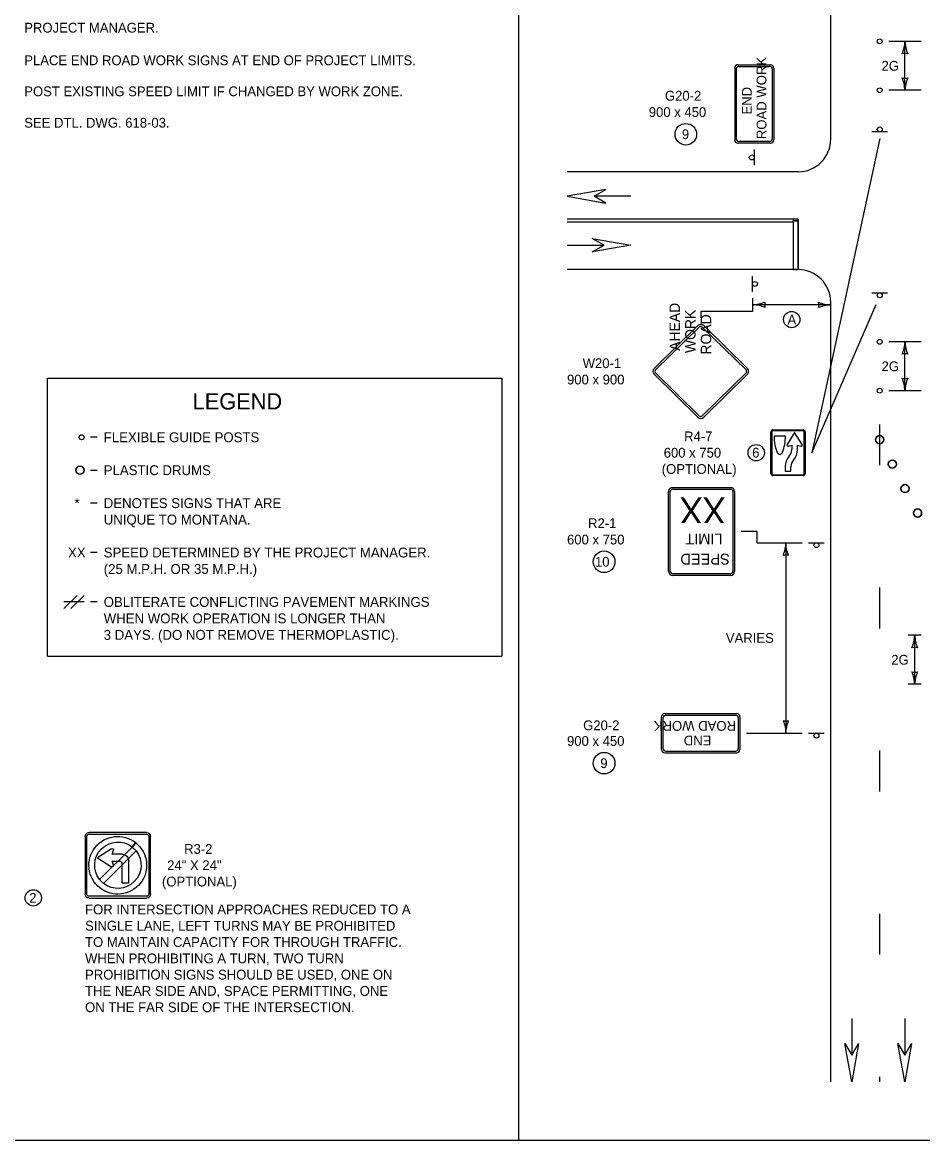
# Model space of a CAD drawing. Extents: x 49991.4 to 50021, y 49987.6 to 50011.4.
# Drawn here: x 50005.02 to 50010.55, y 49987.8 to 49994.66 of the extents above; entities that cross this region are included whole.
import ezdxf

# ---------------------------------------------------------------- set-up
doc = ezdxf.new("R2010")
doc.units = 0
for name, color, linetype in [('Level 1', 7, 'Continuous'), ('Level 2', 7, 'Continuous'), ('Level 25', 7, 'Continuous'), ('Level 3', 7, 'Continuous')]:
    doc.layers.add(name, color=color, linetype=linetype)

# ---------------------------------------------------------------- blocks, each defined once
blk = doc.blocks.new('R3.1')
at = {"layer": 'Level 25'}
for p, q in [((-41.1, 34.2), (-38.9, 34.2)), ((-38.9, 34.2), (-41.1, 34.2)), ((-41.1, -39.9), (-41.1, 34.2)), ((-41.1, 34.2), (-38.9, 34.2)), ((-38.9, 34.2), (-38.9, -39.9)), ((-35.8, 39.5), (38.3, 39.5)), ((38.3, 37.3), (-35.8, 37.3)), ((41.4, -39.9), (41.4, 34.2)), ((43.6, 34.2), (43.6, -39.9)), ((-17.3, 20.7), (-22.3, 15.7)), ((-17.3, 20.7), (-22.3, 15.7)), ((-22.3, 15.7), (19.8, -26.4)), ((-21.9, 26.2), (-17.3, 20.7)), ((-17.2, 20.8), (-21.8, 26.3)), ((24.8, -21.4), (-17.3, 20.7)), ((8.4, 11.3), (6.7, 16.5)), ((9.3, 18.5), (27.7, 6.9)), ((9.3, 18.5), (9.3, 18.5)), ((-12.9, -25.7), (-12.9, 3.3)), ((-4.9, 11.3), (8.4, 11.3)), ((8.4, 2.5), (-1.1, 2.5)), ((6.7, -2.7), (8.4, 2.5)), ((27.7, 6.9), (9.3, -4.7)), ((-4.1, -0.5), (-4.1, -25.7)), ((-4.1, -25.7), (-12.9, -25.7)), ((19.8, -26.4), (24.8, -21.4)), ((19.8, -26.4), (24.8, -21.4)), ((-35.8, -42.9), (38.3, -42.9)), ((38.3, -45.2), (-35.8, -45.2))]:
    blk.add_line(p, q, dxfattribs=at)
for centre, radius, start, end in [((-35.8, 34.2), 5.29, 90, 180), ((-35.8, 34.2), 3.09, 90, 180), ((1.3, -2.9), 37.3, 128.573, 128.3407), ((38.3, 34.2), 5.29, 0, 90), ((38.3, 34.2), 3.09, 0, 90), ((1.2, -2.8), 30, 141.7565, 308.2429), ((1.2, -2.8), 30, 321.7571, 127.9547), ((8.4, 17), 1.75, 57.757, 197.6186), ((1.2, -2.8), 30, 44.2869, 44.4163), ((-4.9, 3.3), 8, 90, 180), ((-1.1, -0.5), 3, 90, 180), ((8.4, -3.2), 1.75, 162.3804, 302.2438), ((1.2, -2.8), 30, 220.8564, 220.8714), ((-35.8, -39.9), 5.29, 180, 270), ((-35.8, -39.9), 3.09, 180, 270), ((38.3, -39.9), 5.29, 270, 0), ((38.3, -39.9), 3.09, 270, 0)]:
    blk.add_arc(centre, radius, start, end, dxfattribs=at)
blk = doc.blocks.new('R4.7')
at = {"layer": 'Level 25'}
for p, q in [((-42.9, -53.4), (-42.9, 48.9)), ((-40.7, 48.9), (-40.7, -53.4)), ((-37.6, 54.2), (36.5, 54.2)), ((36.5, 52), (-37.6, 52)), ((-6.8, 38.4), (-35, 38.4)), ((15.6, 47.6), (-3, 18.2)), ((34.1, 18.2), (15.6, 47.6)), ((39.5, -53.4), (39.5, 48.9)), ((41.7, 48.9), (41.7, -53.4)), ((0.3, 14.1), (8.5, 16.7)), ((8.5, 16.7), (8.5, 5.4)), ((22.6, 5.4), (22.6, 16.7)), ((22.6, 16.7), (30.9, 14.1)), ((-7.6, -36.9), (-7.6, -48.1)), ((-7.6, -48.1), (6.5, -48.1)), ((6.5, -48.1), (6.5, -36.9)), ((-37.6, -56.5), (36.5, -56.5)), ((36.5, -58.7), (-37.6, -58.7))]:
    blk.add_line(p, q, dxfattribs=at)
blk.add_lwpolyline([(15.8, 47.3), (15.5, 47.6)], dxfattribs=at)
for centre, radius, start, end in [((-37.6, 48.9), 5.29, 90, 180), ((-37.6, 48.9), 3.09, 90, 180), ((70.9, 38), 105.8, 179.7952, 201.7879), ((-112.6, 38), 105.8, 338.2124, 0.205), ((36.5, 48.9), 5.29, 0, 90), ((36.5, 48.9), 3.09, 0, 90), ((-0.6, 16.8), 2.79, 147.757, 287.6186), ((-16.2, 5.4), 24.7, 318.1901, 0), ((-16.2, 5.4), 38.8, 318.1901, 0), ((31.8, 16.8), 2.79, 252.3804, 32.2438), ((-20.9, 1.3), 7.06, 201.7877, 338.2132), ((31.2, -36.9), 38.8, 138.1903, 180), ((31.2, -36.9), 24.7, 138.1903, 180), ((-37.6, -53.4), 5.29, 180, 270), ((-37.6, -53.4), 3.09, 180, 270), ((36.5, -53.4), 3.09, 270, 0), ((36.5, -53.4), 5.29, 270, 0)]:
    blk.add_arc(centre, radius, start, end, dxfattribs=at)
blk = doc.blocks.new('ARR')
at = {"layer": 'Level 3'}
for centre, radius, start, end in [((1.5, 37), 37.1, 247.456, 267.6395), ((-21.4, 0), 9.13, 342.1388, 17.8612), ((1.9, -38.8), 38.8, 92.8273, 112.0772)]:
    blk.add_arc(centre, radius, start, end, dxfattribs=at)
blk = doc.blocks.new('G20-2')
at = {"layer": 'Level 1'}
for p, q in [((-0.2403, -0.1004), (-0.2403, 0.0996)), ((-0.2303, -0.0954), (-0.2303, 0.0946)), ((0.2197, 0.1196), (-0.2203, 0.1196)), ((0.2147, 0.1096), (-0.2153, 0.1096)), ((0.2297, 0.0946), (0.2297, -0.0954)), ((0.2397, 0.0996), (0.2397, -0.1004)), ((0.2196, -0.1204), (-0.2204, -0.1204)), ((0.2147, -0.1104), (-0.2153, -0.1104))]:
    blk.add_line(p, q, dxfattribs=at)
for centre, radius, start, end in [((-0.2203, 0.0996), 0.02, 90, 180), ((-0.2153, 0.0946), 0.015, 90, 180), ((0.2147, 0.0946), 0.015, 360, 90), ((0.2197, 0.0996), 0.02, 360, 90), ((-0.2204, -0.1004), 0.02, 180, 270), ((-0.2153, -0.0954), 0.015, 180, 270), ((0.2147, -0.0954), 0.015, 270, 360), ((0.2196, -0.1004), 0.02, 270, 360)]:
    blk.add_arc(centre, radius, start, end, dxfattribs=at)
for s, p in [('END', (-0.0655, 0.015)), ('ROAD WORK', (-0.2162, -0.075))]:
    blk.add_text(s, height=0.06, rotation=360, dxfattribs=at).set_placement(p)

msp = doc.modelspace()

# ---------------------------------------------------------------- linework, layer by layer
at = {"layer": 'Level 1'}
for p, q in [((50008.0668, 49998.9992), (50008.0668, 49987.7988)), ((50009.9832, 49993.9404), (50009.9832, 49998.6295)), ((50010.3314, 49993.9851), (50010.2354, 49993.9851)), ((50009.5136, 49993.8764), (50009.5136, 49993.7804)), ((50009.7832, 49993.7404), (50008.3664, 49993.7404)), ((50008.7565, 49993.5905), (50008.5306, 49993.5905)), ((50008.7565, 49993.5901), (50008.5306, 49993.5901)), ((50009.7832, 49993.4505), (50008.3664, 49993.4505)), ((50009.7532, 49993.4305), (50008.3664, 49993.4305)), ((50009.7532, 49993.4505), (50009.7532, 49993.1404)), ((50009.7532, 49993.4405), (50009.7832, 49993.4405)), ((50009.7832, 49993.4505), (50009.7832, 49993.1404)), ((50008.3664, 49993.2905), (50008.5923, 49993.2905)), ((50008.3664, 49993.2901), (50008.5923, 49993.2901)), ((50009.7832, 49993.1404), (50008.3664, 49993.1404)), ((50009.5032, 49993.0044), (50009.5032, 49993.1004)), ((50010.2353, 49992.9977), (50010.3313, 49992.9977)), ((50009.9832, 49988.1586), (50009.9832, 49992.9404)), ((50008.8993, 49992.5343), (50009.1676, 49992.7971)), ((50008.9079, 49992.5255), (50009.1762, 49992.7883)), ((50009.1949, 49992.7883), (50009.4631, 49992.5255)), ((50009.2035, 49992.7971), (50009.4717, 49992.5343)), ((50009.1676, 49992.2355), (50008.8993, 49992.4983)), ((50009.1762, 49992.2443), (50008.9079, 49992.5071)), ((50009.4631, 49992.5071), (50009.1949, 49992.2443)), ((50009.4717, 49992.4983), (50009.2035, 49992.2355)), ((50010.2833, 49991.9404), (50010.2833, 49992.1904)), ((50010.2583, 49992.0977), (50010.2583, 49992.0977)), ((50010.3358, 49991.9477), (50010.3358, 49991.9477)), ((50008.9879, 49991.2902), (50008.9879, 49991.7797)), ((50008.9984, 49991.2902), (50008.9984, 49991.7797)), ((50009.0132, 49991.805), (50009.3676, 49991.805)), ((50009.0132, 49991.7945), (50009.3676, 49991.7945)), ((50009.3824, 49991.7797), (50009.3824, 49991.2902)), ((50009.393, 49991.7797), (50009.393, 49991.2902)), ((50010.4133, 49991.7977), (50010.4133, 49991.7977)), ((50010.4907, 49991.6477), (50010.4907, 49991.6477)), ((50009.8472, 49991.4657), (50009.9432, 49991.4657)), ((50009.3676, 49991.2755), (50009.0132, 49991.2755)), ((50009.3676, 49991.2649), (50009.0132, 49991.2649)), ((50009.1904, 49991.2649), (50009.1904, 49991.2649)), ((50005.2781, 49991.062), (50005.3589, 49991.1428)), ((50005.321, 49991.062), (50005.4018, 49991.1428)), ((50010.2833, 49990.9404), (50010.2833, 49991.1904)), ((50005.4018, 49991.1024), (50005.2781, 49991.1024)), ((50009.8472, 49990.2977), (50009.9432, 49990.2977)), ((50010.2833, 49989.9404), (50010.2833, 49990.1904)), ((50010.2833, 49988.9404), (50010.2833, 49989.1904)), ((50010.1119, 49988.5487), (50010.1119, 49988.3228)), ((50010.1123, 49988.5487), (50010.1123, 49988.3228)), ((50010.4366, 49988.5487), (50010.4366, 49988.3228)), ((50010.437, 49988.5487), (50010.437, 49988.3228)), ((50010.2833, 49988.1586), (50010.2833, 49988.1904))]:
    msp.add_line(p, q, dxfattribs=at)
for points in [[(49999.3835, 49998.9992), (50016.7501, 49998.9992), (50016.7501, 49987.7988), (49999.3835, 49987.7988)], [(50008.6029, 49993.6321), (50008.3664, 49993.5905), (50008.6029, 49993.5485), (50008.5307, 49993.5905)], [(50008.52, 49993.3321), (50008.7565, 49993.2905), (50008.52, 49993.2485), (50008.5922, 49993.2905)], [(50010.1539, 49988.3951), (50010.1123, 49988.1586), (50010.0703, 49988.3951), (50010.1123, 49988.3229)], [(50010.4786, 49988.3951), (50010.437, 49988.1586), (50010.395, 49988.3951), (50010.437, 49988.3229)]]:
    msp.add_lwpolyline(points, close=True, dxfattribs=at)
for points in [[(50009.7832, 49993.4405), (50009.7832, 49993.4505), (50009.7532, 49993.4505), (50009.7532, 49993.4405), (50009.7832, 49993.4405)], [(50009.7532, 49993.1404), (50009.7832, 49993.1404), (50009.7832, 49993.4405), (50009.7532, 49993.4405), (50009.7532, 49993.1404)]]:
    msp.add_lwpolyline(points, dxfattribs=at)
for centre, radius in [((50010.2833, 49994.5404), 0.015), ((50010.2833, 49994.2404), 0.015), ((50010.2834, 49994.0002), 0.0152), ((50009.4984, 49993.8284), 0.0152), ((50009.5183, 49993.0525), 0.0152), ((50010.2834, 49992.9826), 0.0152), ((50010.2833, 49992.6977), 0.015), ((50010.2833, 49992.3977), 0.015), ((50005.3866, 49992.1124), 0.0152), ((50010.2833, 49992.0977), 0.025), ((50010.3608, 49991.9477), 0.025), ((50005.3766, 49991.9104), 0.0252), ((50010.4382, 49991.7977), 0.025), ((50010.5157, 49991.6477), 0.025), ((50009.8952, 49991.4506), 0.0152), ((50009.8952, 49990.2826), 0.0152)]:
    msp.add_circle(centre, radius, dxfattribs=at)
for centre, radius, start, end in [((50009.7832, 49993.9404), 0.2, 270, 0.00074), ((50009.7832, 49992.9404), 0.2, 359.99985, 90), ((50010.2833, 49992.0977), 0.025, 0, 180), ((50010.2833, 49992.0977), 0.025, 180, 0), ((50010.3608, 49991.9477), 0.025, 0, 180), ((50010.3608, 49991.9477), 0.025, 180, 0), ((50005.3766, 49991.9104), 0.0252, 360, 180), ((50005.3766, 49991.9104), 0.0252, 180, 0), ((50010.4382, 49991.7977), 0.025, 0, 180), ((50009.0132, 49991.7797), 0.0253, 90, 180), ((50009.0132, 49991.7797), 0.0148, 90, 180), ((50009.3676, 49991.7797), 0.0253, 360, 90), ((50009.3676, 49991.7797), 0.0148, 360, 90), ((50010.4382, 49991.7977), 0.025, 180, 0), ((50010.5157, 49991.6477), 0.025, 0, 180), ((50010.5157, 49991.6477), 0.025, 180, 0), ((50009.0132, 49991.2902), 0.0253, 180, 270), ((50009.0132, 49991.2902), 0.0148, 180, 270), ((50009.3676, 49991.2902), 0.0148, 270, 360), ((50009.3676, 49991.2902), 0.0253, 270, 360)]:
    msp.add_arc(centre, radius, start, end, dxfattribs=at)
for centre, major_axis, ratio, start_param, end_param in [((50009.1855, 49992.7792), (0.0255, 0), 0.98963, 0.785394, 2.356194), ((50009.1855, 49992.7792), (0.0132, 0), 0.98, 0.785394, 2.356194), ((50008.9173, 49992.5163), (-0.0255, 0), 0.98963, 5.497795, 7.068583), ((50008.9173, 49992.5163), (-0.0132, 0), 0.98, 5.497795, 7.068583), ((50009.4537, 49992.5163), (0.0132, 0), 0.98, 5.497787, 7.068583), ((50009.4537, 49992.5163), (0.0255, 0), 0.98963, 5.497787, 7.068583), ((50009.1855, 49992.2535), (0.0255, 0), 0.98963, 3.926991, 5.497787), ((50009.1855, 49992.2535), (0.0132, 0), 0.98, 3.926991, 5.497787)]:
    msp.add_ellipse(centre, major_axis=major_axis, ratio=ratio, start_param=start_param, end_param=end_param, dxfattribs=at)
at = {"layer": 'Level 2'}
for p, q in [((50005.1781, 49990.7701), (50005.1781, 49992.4741)), ((50005.4822, 49992.1124), (50005.4418, 49992.1124)), ((50005.4418, 49991.9104), (50005.4822, 49991.9104)), ((50005.4822, 49991.7084), (50005.4418, 49991.7084)), ((50005.4822, 49991.4054), (50005.4418, 49991.4054)), ((50005.4822, 49991.1024), (50005.4418, 49991.1024)), ((50005.1781, 49990.7701), (50007.965, 49990.7701))]:
    msp.add_line(p, q, dxfattribs=at)
msp.add_lwpolyline([(50005.1781, 49992.4741), (50007.965, 49992.4741), (50007.965, 49990.7701)], dxfattribs=at)
for centre, radius in [((50009.094, 49993.9705), 0.0662), ((50009.7432, 49992.8343), 0.0501), ((50009.5253, 49992.0177), 0.0501), ((50008.5923, 49991.3488), 0.0662), ((50008.5923, 49990.1135), 0.0662), ((50005.09, 49989.2877), 0.0501)]:
    msp.add_circle(centre, radius, dxfattribs=at)
at = {"layer": 'Level 3'}
for p, q in [((50010.5382, 49994.5404), (50010.3383, 49994.5404)), ((50010.4382, 49994.2401), (50010.4382, 49994.5404)), ((50010.5382, 49994.2401), (50010.3383, 49994.2401)), ((50010.2834, 49993.945), (50009.8661, 49992.0177)), ((50009.5032, 49992.9644), (50009.5032, 49992.8844)), ((50009.9832, 49992.9244), (50009.5032, 49992.9244)), ((50009.8661, 49992.0177), (50010.2607, 49992.9273)), ((50009.1855, 49992.8844), (50009.1855, 49992.8444)), ((50009.5032, 49992.8844), (50009.1855, 49992.8844)), ((50010.5382, 49992.6977), (50010.3383, 49992.6977)), ((50010.4382, 49992.3977), (50010.4382, 49992.6977)), ((50010.5382, 49992.3977), (50010.3383, 49992.3977)), ((50009.5306, 49991.4657), (50009.8072, 49991.4657)), ((50009.7072, 49991.4657), (50009.7072, 49990.2977)), ((50010.5381, 49990.898), (50010.4581, 49990.898)), ((50010.4981, 49990.5977), (50010.4981, 49990.898)), ((50010.5381, 49990.5977), (50010.4581, 49990.5977)), ((50009.4656, 49990.2977), (50009.8072, 49990.2977))]:
    msp.add_line(p, q, dxfattribs=at)
msp.add_lwpolyline([(50009.5306, 49991.4657), (50009.5306, 49991.535), (50009.433, 49991.535)], dxfattribs=at)
for centre, radius, start, end in [((50010.2159, 49994.5496), 0.2225, 337.45601, 357.63952), ((50010.6712, 49994.5519), 0.2332, 182.82731, 202.07716), ((50010.4382, 49994.4121), 0.0548, 72.13882, 107.86118), ((50010.4382, 49994.3685), 0.0548, 252.13882, 287.86118), ((50010.2053, 49994.2286), 0.2332, 2.82731, 22.07716), ((50010.6606, 49994.2309), 0.2225, 157.45601, 177.63952), ((50010.2159, 49992.7069), 0.2225, 337.45601, 357.63952), ((50010.6712, 49992.7092), 0.2332, 182.82731, 202.07716), ((50010.4382, 49992.5694), 0.0548, 72.13882, 107.86118), ((50010.4382, 49992.526), 0.0548, 252.13882, 287.86118), ((50010.2053, 49992.3862), 0.2332, 2.82731, 22.07716), ((50010.6606, 49992.3885), 0.2225, 157.45601, 177.63952), ((50010.2757, 49990.9072), 0.2225, 337.45601, 357.63952), ((50010.731, 49990.9095), 0.2332, 182.82731, 202.07716), ((50010.4981, 49990.7697), 0.0548, 72.13882, 107.86118), ((50010.4981, 49990.726), 0.0548, 252.13882, 287.86118), ((50010.2652, 49990.5862), 0.2332, 2.82731, 22.07716), ((50010.7205, 49990.5885), 0.2225, 157.45601, 177.63952)]:
    msp.add_arc(centre, radius, start, end, dxfattribs=at)

# ---------------------------------------------------------------- block references
at = {"layer": 'Level 1', "xscale": 0.002488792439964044, "yscale": 0.002488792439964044}
msp.add_blockref('R4.7', (50009.7222, 49992.0232), dxfattribs=at)
at = {"layer": 'Level 1', "xscale": 0.004746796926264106, "yscale": -0.004746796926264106, "rotation": 179.9999999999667}
msp.add_blockref('R3.1', (50005.6145, 49989.5011), dxfattribs=at)
at = {"layer": 'Level 2'}
for p, xscale, yscale, rotation in [((50009.5032, 49992.9244), 0.005999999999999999, 0.006, -179.99999999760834), ((50009.9832, 49992.9244), 0.005999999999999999, 0.006, 2.3916545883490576e-09), ((50009.7072, 49991.4657), 0.006, -0.006, 90), ((50009.7072, 49990.2977), 0.006, -0.006, -90)]:
    msp.add_blockref('ARR', p, dxfattribs=dict(at, xscale=xscale, yscale=yscale, rotation=rotation))
at = {"layer": 'Level 3', "xscale": 1.001, "yscale": 1.001}
for p, rotation in [((50009.5132, 49994.157), 90), ((50009.185, 49990.2973), 179.99999999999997)]:
    msp.add_blockref('G20-2', p, dxfattribs=dict(at, rotation=rotation))

# ---------------------------------------------------------------- texts
at = {"layer": 'Level 1'}
for s, height, rotation, p in [('AHEAD', 0.06395, 90, (50009.0577, 49992.6422)), ('WORK', 0.06395, 90, (50009.1535, 49992.6285)), ('ROAD', 0.06395, 90, (50009.2494, 49992.6196)), ('XX', 0.15772, 180, (50009.3375, 49991.7439)), ('LIMIT', 0.06695, 180, (50009.3192, 49991.5219)), ('SPEED', 0.06695, 180, (50009.3635, 49991.3982))]:
    msp.add_text(s, height=height, rotation=rotation, dxfattribs=at).set_placement(p)
at = {"layer": 'Level 2'}
for s, height, p in [('PROJECT MANAGER.', 0.06, (50005.0345, 49994.5941)), ('PLACE END ROAD WORK SIGNS AT END OF PROJECT LIMITS.', 0.06, (50005.0345, 49994.3941)), ('2G', 0.06006, (50010.2945, 49994.3602)), ('POST EXISTING SPEED LIMIT IF CHANGED BY WORK ZONE.', 0.06, (50005.0345, 49994.2039)), ('G20-2', 0.06, (50008.9654, 49994.1767)), ('900 x 450', 0.06, (50008.8665, 49994.0767)), ('SEE DTL. DWG. 618-03.', 0.06, (50005.0345, 49994.0112)), ('9', 0.0601, (50009.0694, 49993.9404)), ('2G', 0.06006, (50010.2945, 49992.5177)), ('LEGEND', 0.1, (50006.0672, 49992.2827)), ('FLEXIBLE GUIDE POSTS', 0.0606, (50005.5222, 49992.0821)), ('R4-7', 0.06, (50009.0831, 49992.0877)), ('600 x 750', 0.06, (50008.958, 49991.9877)), ('6', 0.06, (50009.5007, 49991.9877)), ('(OPTIONAL)', 0.06, (50008.9458, 49991.8877)), ('PLASTIC DRUMS', 0.0606, (50005.5222, 49991.8801)), ('*', 0.0607, (50005.3425, 49991.678)), ('DENOTES SIGNS THAT ARE', 0.0606, (50005.5222, 49991.6781)), ('UNIQUE TO MONTANA.', 0.0606, (50005.5222, 49991.5771)), ('R2-1', 0.06, (50008.494, 49991.555)), ('600 x 750', 0.06, (50008.3648, 49991.455)), ('XX', 0.0606, (50005.303, 49991.3751)), ('SPEED DETERMINED BY THE PROJECT MANAGER.', 0.0606, (50005.5222, 49991.3751)), ('(25 M.P.H. OR 35 M.P.H.)', 0.0606, (50005.5222, 49991.2741)), ('10', 0.06006, (50008.5361, 49991.3189)), ('OBLITERATE CONFLICTING PAVEMENT MARKINGS', 0.0606, (50005.5222, 49991.0721)), ('WHEN WORK OPERATION IS LONGER THAN', 0.0606, (50005.5222, 49990.9711)), ('3 DAYS. (DO NOT REMOVE THERMOPLASTIC).', 0.0606, (50005.5222, 49990.8701)), ('2G', 0.06006, (50010.3543, 49990.7178)), ('G20-2', 0.06, (50008.4636, 49990.3157)), ('900 x 450', 0.06, (50008.3648, 49990.2197)), ('9', 0.0601, (50008.5691, 49990.0836)), ('R3-2', 0.06, (50006.0154, 49989.5576)), ('24" X 24"', 0.06, (50005.9115, 49989.4576)), ('(OPTIONAL)', 0.06, (50005.8795, 49989.3576)), ('2', 0.06, (50005.0649, 49989.2577)), ('FOR INTERSECTION APPROACHES REDUCED TO A', 0.06, (50005.4077, 49989.1867)), ('SINGLE LANE, LEFT TURNS MAY BE PROHIBITED', 0.06, (50005.4077, 49989.0867)), ('TO MAINTAIN CAPACITY FOR THROUGH TRAFFIC.', 0.06, (50005.4077, 49988.9867)), ('WHEN PROHIBITING A TURN, TWO TURN ', 0.06, (50005.4077, 49988.8867)), ('PROHIBITION SIGNS SHOULD BE USED, ONE ON ', 0.06, (50005.4077, 49988.7867)), ('THE NEAR SIDE AND, SPACE PERMITTING, ONE ', 0.06, (50005.4077, 49988.6867)), ('ON THE FAR SIDE OF THE INTERSECTION.', 0.06, (50005.4077, 49988.5867))]:
    msp.add_text(s, height=height, dxfattribs=at).set_placement(p)
for s, rotation, p in [('A', 0, (50009.7174, 49992.8043)), ('W20-1', 360, (50008.4607, 49992.5363)), ('900 x 900', 360, (50008.3648, 49992.4363)), ('VARIES', 360, (50009.3392, 49990.8517))]:
    msp.add_text(s, height=0.06, rotation=rotation, dxfattribs=at).set_placement(p)

doc.saveas('drawing.dxf')
